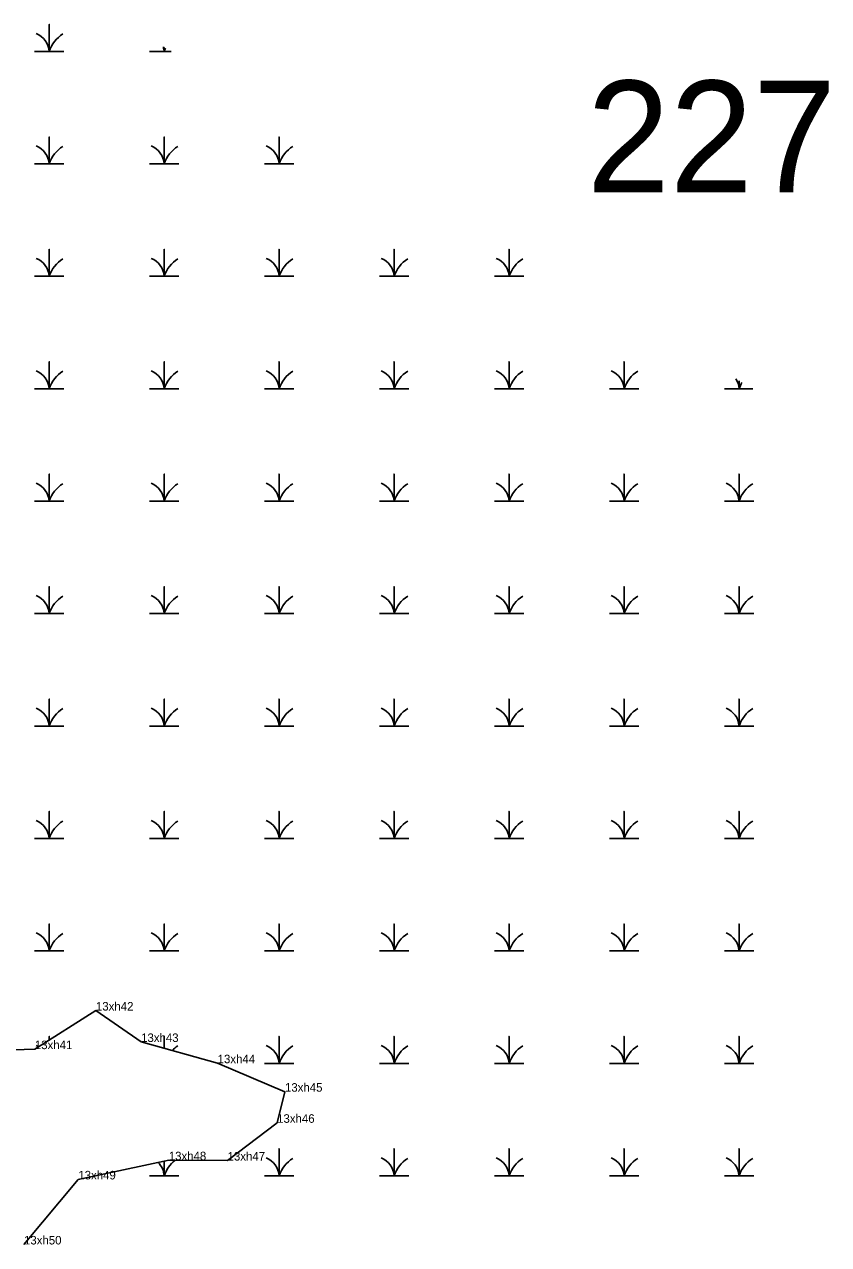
# Model space of a CAD drawing. Extents: x 2072529 to 2268796, y 436423 to 470406.
# Drawn here: x 2248750 to 2249221, y 446231 to 446945 of the extents above; entities that cross this region are included whole.
import ezdxf

# ---------------------------------------------------------------- set-up
doc = ezdxf.new("R2010")
doc.units = 0
for name, color, linetype in [('Default', 7, 'Continuous'), ('Exist Environmental Wetland Boundary', 7, 'Continuous'), ('Exist Environmental Wetland Boundary Cogo Comment', 7, 'Continuous'), ('Exist Hydro Swamp or Marsh', 7, 'Continuous'), ('Old_Level_20', 7, 'Continuous')]:
    doc.layers.add(name, color=color, linetype=linetype)

msp = doc.modelspace()

# ---------------------------------------------------------------- linework, layer by layer
at = {"layer": 'Exist Environmental Wetland Boundary'}
msp.add_lwpolyline([(2248713.09, 446344.22), (2248756.47, 446345.67), (2248792.2, 446368.25), (2248818.62, 446349.86), (2248863.37, 446337.42), (2248902.77, 446320.77), (2248898.16, 446302.57), (2248869.21, 446280.49), (2248834.79, 446280.65), (2248781.89, 446269.44), (2248750.12, 446231.37)], dxfattribs=at)
at = {"layer": 'Exist Hydro Swamp or Marsh'}
for points in [[(2248756.26, 446929.57), (2248764.86, 446929.57), (2248764.86, 446945.35), (2248764.86, 446929.57), (2248773.47, 446929.57)], [(2248823.51, 446929.57), (2248832.11, 446929.57), (2248832.11, 446931.89)], [(2248832.11, 446931.89), (2248832.11, 446929.57), (2248836.12, 446929.57)], [(2248756.26, 446863.77), (2248764.86, 446863.77), (2248764.86, 446879.55), (2248764.86, 446863.77), (2248773.47, 446863.77)], [(2248823.51, 446863.77), (2248832.11, 446863.77), (2248832.11, 446879.55), (2248832.11, 446863.77), (2248840.72, 446863.77)], [(2248890.76, 446863.77), (2248899.36, 446863.77), (2248899.36, 446879.55), (2248899.36, 446863.77), (2248907.97, 446863.77)], [(2248756.26, 446797.97), (2248764.86, 446797.97), (2248764.86, 446813.75), (2248764.86, 446797.97), (2248773.47, 446797.97)], [(2248823.51, 446797.97), (2248832.11, 446797.97), (2248832.11, 446813.75), (2248832.11, 446797.97), (2248840.72, 446797.97)], [(2248890.76, 446797.97), (2248899.36, 446797.97), (2248899.36, 446813.75), (2248899.36, 446797.97), (2248907.97, 446797.97)], [(2248958.01, 446797.97), (2248966.61, 446797.97), (2248966.61, 446813.75), (2248966.61, 446797.97), (2248975.22, 446797.97)], [(2249025.26, 446797.97), (2249033.86, 446797.97), (2249033.86, 446813.75), (2249033.86, 446797.97), (2249042.47, 446797.97)], [(2248756.26, 446732.17), (2248764.86, 446732.17), (2248764.86, 446747.95), (2248764.86, 446732.17), (2248773.47, 446732.17)], [(2248823.51, 446732.17), (2248832.11, 446732.17), (2248832.11, 446747.95), (2248832.11, 446732.17), (2248840.72, 446732.17)], [(2248890.76, 446732.17), (2248899.36, 446732.17), (2248899.36, 446747.95), (2248899.36, 446732.17), (2248907.97, 446732.17)], [(2248958.01, 446732.17), (2248966.61, 446732.17), (2248966.61, 446747.95), (2248966.61, 446732.17), (2248975.22, 446732.17)], [(2249025.26, 446732.17), (2249033.86, 446732.17), (2249033.86, 446747.95), (2249033.86, 446732.17), (2249042.47, 446732.17)], [(2249092.51, 446732.17), (2249101.11, 446732.17), (2249101.11, 446747.95), (2249101.11, 446732.17), (2249109.72, 446732.17)], [(2249159.76, 446732.17), (2249168.36, 446732.17), (2249168.36, 446736.85)], [(2249168.36, 446736.85), (2249168.36, 446732.17), (2249176.45, 446732.17)], [(2248756.26, 446666.37), (2248764.86, 446666.37), (2248764.86, 446682.15), (2248764.86, 446666.37), (2248773.47, 446666.37)], [(2248823.51, 446666.37), (2248832.11, 446666.37), (2248832.11, 446682.15), (2248832.11, 446666.37), (2248840.72, 446666.37)], [(2248890.76, 446666.37), (2248899.36, 446666.37), (2248899.36, 446682.15), (2248899.36, 446666.37), (2248907.97, 446666.37)], [(2248958.01, 446666.37), (2248966.61, 446666.37), (2248966.61, 446682.15), (2248966.61, 446666.37), (2248975.22, 446666.37)], [(2249025.26, 446666.37), (2249033.86, 446666.37), (2249033.86, 446682.15), (2249033.86, 446666.37), (2249042.47, 446666.37)], [(2249092.51, 446666.37), (2249101.11, 446666.37), (2249101.11, 446682.15), (2249101.11, 446666.37), (2249109.72, 446666.37)], [(2249159.76, 446666.37), (2249168.36, 446666.37), (2249168.36, 446682.15), (2249168.36, 446666.37), (2249176.97, 446666.37)], [(2248756.26, 446600.57), (2248764.86, 446600.57), (2248764.86, 446616.35), (2248764.86, 446600.57), (2248773.47, 446600.57)], [(2248823.51, 446600.57), (2248832.11, 446600.57), (2248832.11, 446616.35), (2248832.11, 446600.57), (2248840.72, 446600.57)], [(2248890.76, 446600.57), (2248899.36, 446600.57), (2248899.36, 446616.35), (2248899.36, 446600.57), (2248907.97, 446600.57)], [(2248958.01, 446600.57), (2248966.61, 446600.57), (2248966.61, 446616.35), (2248966.61, 446600.57), (2248975.22, 446600.57)], [(2249025.26, 446600.57), (2249033.86, 446600.57), (2249033.86, 446616.35), (2249033.86, 446600.57), (2249042.47, 446600.57)], [(2249092.51, 446600.57), (2249101.11, 446600.57), (2249101.11, 446616.35), (2249101.11, 446600.57), (2249109.72, 446600.57)], [(2249159.76, 446600.57), (2249168.36, 446600.57), (2249168.36, 446616.35), (2249168.36, 446600.57), (2249176.97, 446600.57)], [(2248756.26, 446534.77), (2248764.86, 446534.77), (2248764.86, 446550.55), (2248764.86, 446534.77), (2248773.47, 446534.77)], [(2248823.51, 446534.77), (2248832.11, 446534.77), (2248832.11, 446550.55), (2248832.11, 446534.77), (2248840.72, 446534.77)], [(2248890.76, 446534.77), (2248899.36, 446534.77), (2248899.36, 446550.55), (2248899.36, 446534.77), (2248907.97, 446534.77)], [(2248958.01, 446534.77), (2248966.61, 446534.77), (2248966.61, 446550.55), (2248966.61, 446534.77), (2248975.22, 446534.77)], [(2249025.26, 446534.77), (2249033.86, 446534.77), (2249033.86, 446550.55), (2249033.86, 446534.77), (2249042.47, 446534.77)], [(2249092.51, 446534.77), (2249101.11, 446534.77), (2249101.11, 446550.55), (2249101.11, 446534.77), (2249109.72, 446534.77)], [(2249159.76, 446534.77), (2249168.36, 446534.77), (2249168.36, 446550.55), (2249168.36, 446534.77), (2249176.97, 446534.77)], [(2248756.26, 446468.97), (2248764.86, 446468.97), (2248764.86, 446484.75), (2248764.86, 446468.97), (2248773.47, 446468.97)], [(2248823.51, 446468.97), (2248832.11, 446468.97), (2248832.11, 446484.75), (2248832.11, 446468.97), (2248840.72, 446468.97)], [(2248890.76, 446468.97), (2248899.36, 446468.97), (2248899.36, 446484.75), (2248899.36, 446468.97), (2248907.97, 446468.97)], [(2248958.01, 446468.97), (2248966.61, 446468.97), (2248966.61, 446484.75), (2248966.61, 446468.97), (2248975.22, 446468.97)], [(2249025.26, 446468.97), (2249033.86, 446468.97), (2249033.86, 446484.75), (2249033.86, 446468.97), (2249042.47, 446468.97)], [(2249092.51, 446468.97), (2249101.11, 446468.97), (2249101.11, 446484.75), (2249101.11, 446468.97), (2249109.72, 446468.97)], [(2249159.76, 446468.97), (2249168.36, 446468.97), (2249168.36, 446484.75), (2249168.36, 446468.97), (2249176.97, 446468.97)], [(2248756.26, 446403.17), (2248764.86, 446403.17), (2248764.86, 446418.95), (2248764.86, 446403.17), (2248773.47, 446403.17)], [(2248823.51, 446403.17), (2248832.11, 446403.17), (2248832.11, 446418.95), (2248832.11, 446403.17), (2248840.72, 446403.17)], [(2248890.76, 446403.17), (2248899.36, 446403.17), (2248899.36, 446418.95), (2248899.36, 446403.17), (2248907.97, 446403.17)], [(2248958.01, 446403.17), (2248966.61, 446403.17), (2248966.61, 446418.95), (2248966.61, 446403.17), (2248975.22, 446403.17)], [(2249025.26, 446403.17), (2249033.86, 446403.17), (2249033.86, 446418.95), (2249033.86, 446403.17), (2249042.47, 446403.17)], [(2249092.51, 446403.17), (2249101.11, 446403.17), (2249101.11, 446418.95), (2249101.11, 446403.17), (2249109.72, 446403.17)], [(2249159.76, 446403.17), (2249168.36, 446403.17), (2249168.36, 446418.95), (2249168.36, 446403.17), (2249176.97, 446403.17)], [(2248764.86, 446350.98), (2248764.86, 446353.15), (2248764.86, 446350.98)], [(2248832.11, 446346.11), (2248832.11, 446353.15), (2248832.11, 446346.11)], [(2248890.76, 446337.37), (2248899.36, 446337.37), (2248899.36, 446353.15), (2248899.36, 446337.37), (2248907.97, 446337.37)], [(2248958.01, 446337.37), (2248966.61, 446337.37), (2248966.61, 446353.15), (2248966.61, 446337.37), (2248975.22, 446337.37)], [(2249025.26, 446337.37), (2249033.86, 446337.37), (2249033.86, 446353.15), (2249033.86, 446337.37), (2249042.47, 446337.37)], [(2249092.51, 446337.37), (2249101.11, 446337.37), (2249101.11, 446353.15), (2249101.11, 446337.37), (2249109.72, 446337.37)], [(2249159.76, 446337.37), (2249168.36, 446337.37), (2249168.36, 446353.15), (2249168.36, 446337.37), (2249176.97, 446337.37)], [(2248890.76, 446271.57), (2248899.36, 446271.57), (2248899.36, 446287.35), (2248899.36, 446271.57), (2248907.97, 446271.57)], [(2248958.01, 446271.57), (2248966.61, 446271.57), (2248966.61, 446287.35), (2248966.61, 446271.57), (2248975.22, 446271.57)], [(2249025.26, 446271.57), (2249033.86, 446271.57), (2249033.86, 446287.35), (2249033.86, 446271.57), (2249042.47, 446271.57)], [(2249092.51, 446271.57), (2249101.11, 446271.57), (2249101.11, 446287.35), (2249101.11, 446271.57), (2249109.72, 446271.57)], [(2249159.76, 446271.57), (2249168.36, 446271.57), (2249168.36, 446287.35), (2249168.36, 446271.57), (2249176.97, 446271.57)], [(2248823.51, 446271.57), (2248832.11, 446271.57), (2248832.11, 446280.09)], [(2248832.11, 446280.09), (2248832.11, 446271.57), (2248840.72, 446271.57)]]:
    msp.add_lwpolyline(points, dxfattribs=at)
for centre, radius, start, end in [((2248752.6, 446928.68), 12.3, 4.14034, 67.53497), ((2248783.11, 446923.5), 19.22, 122.12745, 161.62219), ((2248819.85, 446928.68), 12.3, 4.14034, 16.44871), ((2248850.36, 446923.5), 19.22, 155.56501, 161.62219), ((2248752.6, 446862.88), 12.3, 4.14034, 67.53497), ((2248783.11, 446857.7), 19.22, 122.12745, 161.62219), ((2248819.85, 446862.88), 12.3, 4.14034, 67.53497), ((2248850.36, 446857.7), 19.22, 122.12745, 161.62219), ((2248887.1, 446862.88), 12.3, 4.14034, 67.53497), ((2248917.61, 446857.7), 19.22, 122.12745, 161.62219), ((2248752.6, 446797.08), 12.3, 4.14034, 67.53497), ((2248783.11, 446791.9), 19.22, 122.12745, 161.62219), ((2248819.85, 446797.08), 12.3, 4.14034, 67.53497), ((2248850.36, 446791.9), 19.22, 122.12745, 161.62219), ((2248887.1, 446797.08), 12.3, 4.14034, 67.53497), ((2248917.61, 446791.9), 19.22, 122.12745, 161.62219), ((2248954.35, 446797.08), 12.3, 4.14034, 67.53497), ((2248984.86, 446791.9), 19.22, 122.12745, 161.62219), ((2249021.6, 446797.08), 12.3, 4.14034, 67.53497), ((2249052.11, 446791.9), 19.22, 122.12745, 161.62219), ((2248752.6, 446731.28), 12.3, 4.14034, 67.53497), ((2248783.11, 446726.1), 19.22, 122.12745, 161.62219), ((2248819.85, 446731.28), 12.3, 4.14034, 67.53497), ((2248850.36, 446726.1), 19.22, 122.12745, 161.62219), ((2248887.1, 446731.28), 12.3, 4.14034, 67.53497), ((2248917.61, 446726.1), 19.22, 122.12745, 161.62219), ((2248954.35, 446731.28), 12.3, 4.14034, 67.53497), ((2248984.86, 446726.1), 19.22, 122.12745, 161.62219), ((2249021.6, 446731.28), 12.3, 4.14034, 67.53497), ((2249052.11, 446726.1), 19.22, 122.12745, 161.62219), ((2249088.85, 446731.28), 12.3, 4.14034, 67.53497), ((2249119.36, 446726.1), 19.22, 122.12745, 161.62219), ((2249156.1, 446731.28), 12.3, 4.14034, 33.08524), ((2249186.61, 446726.1), 19.22, 149.45416, 161.62219), ((2248752.6, 446665.48), 12.3, 4.14034, 67.53497), ((2248783.11, 446660.3), 19.22, 122.12745, 161.62219), ((2248819.85, 446665.48), 12.3, 4.14034, 67.53497), ((2248850.36, 446660.3), 19.22, 122.12745, 161.62219), ((2248887.1, 446665.48), 12.3, 4.14034, 67.53497), ((2248917.61, 446660.3), 19.22, 122.12745, 161.62219), ((2248954.35, 446665.48), 12.3, 4.14034, 67.53497), ((2248984.86, 446660.3), 19.22, 122.12745, 161.62219), ((2249021.6, 446665.48), 12.3, 4.14034, 67.53497), ((2249052.11, 446660.3), 19.22, 122.12745, 161.62219), ((2249088.85, 446665.48), 12.3, 4.14034, 67.53497), ((2249119.36, 446660.3), 19.22, 122.12745, 161.62219), ((2249156.1, 446665.48), 12.3, 4.14034, 67.53497), ((2249186.61, 446660.3), 19.22, 122.12745, 161.62219), ((2248752.6, 446599.68), 12.3, 4.14034, 67.53497), ((2248783.11, 446594.5), 19.22, 122.12745, 161.62219), ((2248819.85, 446599.68), 12.3, 4.14034, 67.53497), ((2248850.36, 446594.5), 19.22, 122.12745, 161.62219), ((2248887.1, 446599.68), 12.3, 4.14034, 67.53497), ((2248917.61, 446594.5), 19.22, 122.12745, 161.62219), ((2248954.35, 446599.68), 12.3, 4.14034, 67.53497), ((2248984.86, 446594.5), 19.22, 122.12745, 161.62219), ((2249021.6, 446599.68), 12.3, 4.14034, 67.53497), ((2249052.11, 446594.5), 19.22, 122.12745, 161.62219), ((2249088.85, 446599.68), 12.3, 4.14034, 67.53497), ((2249119.36, 446594.5), 19.22, 122.12745, 161.62219), ((2249156.1, 446599.68), 12.3, 4.14034, 67.53497), ((2249186.61, 446594.5), 19.22, 122.12745, 161.62219), ((2248752.6, 446533.88), 12.3, 4.14034, 67.53497), ((2248783.11, 446528.7), 19.22, 122.12745, 161.62219), ((2248819.85, 446533.88), 12.3, 4.14034, 67.53497), ((2248850.36, 446528.7), 19.22, 122.12745, 161.62219), ((2248887.1, 446533.88), 12.3, 4.14034, 67.53497), ((2248917.61, 446528.7), 19.22, 122.12745, 161.62219), ((2248954.35, 446533.88), 12.3, 4.14034, 67.53497), ((2248984.86, 446528.7), 19.22, 122.12745, 161.62219), ((2249021.6, 446533.88), 12.3, 4.14034, 67.53497), ((2249052.11, 446528.7), 19.22, 122.12745, 161.62219), ((2249088.85, 446533.88), 12.3, 4.14034, 67.53497), ((2249119.36, 446528.7), 19.22, 122.12745, 161.62219), ((2249156.1, 446533.88), 12.3, 4.14034, 67.53497), ((2249186.61, 446528.7), 19.22, 122.12745, 161.62219), ((2248752.6, 446468.08), 12.3, 4.14034, 67.53497), ((2248783.11, 446462.9), 19.22, 122.12745, 161.62219), ((2248819.85, 446468.08), 12.3, 4.14034, 67.53497), ((2248850.36, 446462.9), 19.22, 122.12745, 161.62219), ((2248887.1, 446468.08), 12.3, 4.14034, 67.53497), ((2248917.61, 446462.9), 19.22, 122.12745, 161.62219), ((2248954.35, 446468.08), 12.3, 4.14034, 67.53497), ((2248984.86, 446462.9), 19.22, 122.12745, 161.62219), ((2249021.6, 446468.08), 12.3, 4.14034, 67.53497), ((2249052.11, 446462.9), 19.22, 122.12745, 161.62219), ((2249088.85, 446468.08), 12.3, 4.14034, 67.53497), ((2249119.36, 446462.9), 19.22, 122.12745, 161.62219), ((2249156.1, 446468.08), 12.3, 4.14034, 67.53497), ((2249186.61, 446462.9), 19.22, 122.12745, 161.62219), ((2248752.6, 446402.28), 12.3, 4.14034, 67.53497), ((2248783.11, 446397.1), 19.22, 122.12745, 161.62219), ((2248819.85, 446402.28), 12.3, 4.14034, 67.53497), ((2248850.36, 446397.1), 19.22, 122.12745, 161.62219), ((2248887.1, 446402.28), 12.3, 4.14034, 67.53497), ((2248917.61, 446397.1), 19.22, 122.12745, 161.62219), ((2248954.35, 446402.28), 12.3, 4.14034, 67.53497), ((2248984.86, 446397.1), 19.22, 122.12745, 161.62219), ((2249021.6, 446402.28), 12.3, 4.14034, 67.53497), ((2249052.11, 446397.1), 19.22, 122.12745, 161.62219), ((2249088.85, 446402.28), 12.3, 4.14034, 67.53497), ((2249119.36, 446397.1), 19.22, 122.12745, 161.62219), ((2249156.1, 446402.28), 12.3, 4.14034, 67.53497), ((2249186.61, 446397.1), 19.22, 122.12745, 161.62219), ((2248752.6, 446336.48), 12.3, 59.921, 67.53497), ((2248850.36, 446331.3), 19.22, 122.12745, 135.26583), ((2248887.1, 446336.48), 12.3, 4.14034, 67.53497), ((2248917.61, 446331.3), 19.22, 122.12745, 161.62219), ((2248954.35, 446336.48), 12.3, 4.14034, 67.53497), ((2248984.86, 446331.3), 19.22, 122.12745, 161.62219), ((2249021.6, 446336.48), 12.3, 4.14034, 67.53497), ((2249052.11, 446331.3), 19.22, 122.12745, 161.62219), ((2249088.85, 446336.48), 12.3, 4.14034, 67.53497), ((2249119.36, 446331.3), 19.22, 122.12745, 161.62219), ((2249156.1, 446336.48), 12.3, 4.14034, 67.53497), ((2249186.61, 446331.3), 19.22, 122.12745, 161.62219), ((2248850.36, 446265.5), 19.22, 128.0854, 161.62219), ((2248887.1, 446270.68), 12.3, 4.14034, 67.53497), ((2248917.61, 446265.5), 19.22, 122.12745, 161.62219), ((2248954.35, 446270.68), 12.3, 4.14034, 67.53497), ((2248984.86, 446265.5), 19.22, 122.12745, 161.62219), ((2249021.6, 446270.68), 12.3, 4.14034, 67.53497), ((2249052.11, 446265.5), 19.22, 122.12745, 161.62219), ((2249088.85, 446270.68), 12.3, 4.14034, 67.53497), ((2249119.36, 446265.5), 19.22, 122.12745, 161.62219), ((2249156.1, 446270.68), 12.3, 4.14034, 67.53497), ((2249186.61, 446265.5), 19.22, 122.12745, 161.62219), ((2248819.85, 446270.68), 12.3, 4.14034, 44.7549)]:
    msp.add_arc(centre, radius, start, end, dxfattribs=at)
at = {"layer": 'Old_Level_20'}
for p, q in [((2248792.2, 446368.25), (2248792.2, 446368.25)), ((2248756.47, 446345.67), (2248756.47, 446345.67)), ((2248818.62, 446349.86), (2248818.62, 446349.86)), ((2248863.37, 446337.42), (2248863.37, 446337.42)), ((2248902.77, 446320.77), (2248902.77, 446320.77)), ((2248898.16, 446302.57), (2248898.16, 446302.57)), ((2248834.79, 446280.65), (2248834.79, 446280.65)), ((2248869.21, 446280.49), (2248869.21, 446280.49)), ((2248781.89, 446269.44), (2248781.89, 446269.44))]:
    msp.add_line(p, q, dxfattribs=at)

# ---------------------------------------------------------------- texts
at = {"layer": 'Default'}
msp.add_text('227', height=65.34, dxfattribs=at).set_placement((2249079.33, 446847.05))
at = {"layer": 'Exist Environmental Wetland Boundary Cogo Comment'}
for s, p in [('13xh42', (2248792.2, 446368.25)), ('13xh43', (2248818.62, 446349.86)), ('13xh41', (2248756.47, 446345.67)), ('13xh44', (2248863.37, 446337.42)), ('13xh45', (2248902.77, 446320.77)), ('13xh46', (2248898.16, 446302.57)), ('13xh48', (2248834.79, 446280.65)), ('13xh47', (2248869.21, 446280.49)), ('13xh49', (2248781.89, 446269.44)), ('13xh50', (2248750.12, 446231.37))]:
    msp.add_text(s, height=5, dxfattribs=at).set_placement(p)

doc.saveas('drawing.dxf')
